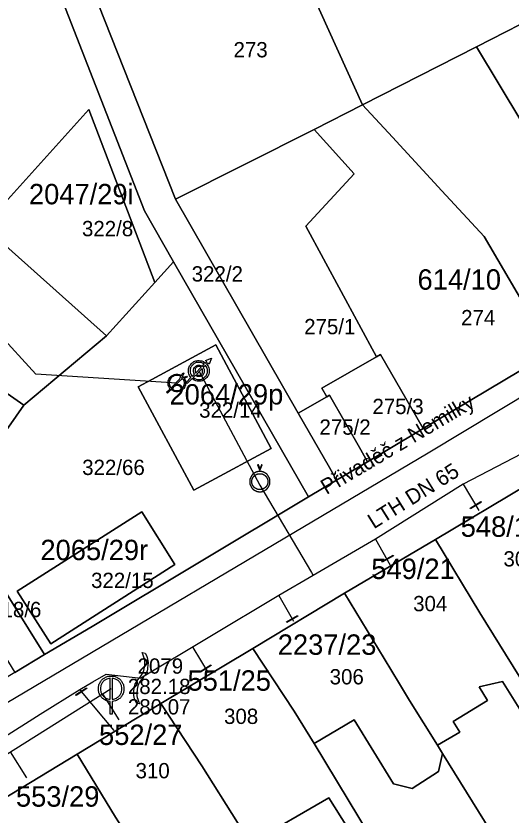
# Model space of a CAD drawing. Extents: x -571312 to -571060, y -1087128 to -1086933.
# Drawn here: x -571251.9 to -571203.4, y -1087085.5 to -1087007.2 of the extents above; entities that cross this region are included whole.
import ezdxf

# ---------------------------------------------------------------- set-up
doc = ezdxf.new("R2010")
doc.units = 0
for name, color, linetype in [('Adresní místo-text', 7, 'Continuous'), ('Armatura vodovodní', 7, 'Continuous'), ('Default', 7, 'Continuous'), ('Kanalizační přípojka', 7, 'Continuous'), ('Kanalizační stoka', 7, 'Continuous'), ('Kanalizační šachta', 7, 'Continuous'), ('Odběrné místo', 7, 'Continuous'), ('Odběrné místo na kanalizaci', 7, 'Continuous'), ('Parcela-polygon', 7, 'Continuous'), ('Parcela-text', 7, 'Continuous'), ('Popis šachty', 7, 'Continuous'), ('Vodovodní přípojka', 7, 'Continuous'), ('Vodovodní řad', 7, 'Continuous'), ('Vodovodní šachta', 7, 'Continuous'), ('Změna stáří vedení', 7, 'Continuous'), ('Řad vodovodní označení', 7, 'Continuous'), ('Řad vodovodní popis', 7, 'Continuous')]:
    doc.layers.add(name, color=color, linetype=linetype)

msp = doc.modelspace()

# ---------------------------------------------------------------- linework, layer by layer
at = {"layer": 'Armatura vodovodní'}
for points in [[(-571206.333, -1087054.873), (-571207.404, -1087055.518), (-571207.445, -1087055.451), (-571206.374, -1087054.806), (-571206.333, -1087054.873)], [(-571214.955, -1087060.142), (-571216.043, -1087060.757), (-571216.082, -1087060.689), (-571214.993, -1087060.074), (-571214.955, -1087060.142)], [(-571224.303, -1087066.06), (-571225.392, -1087066.674), (-571225.43, -1087066.606), (-571224.341, -1087065.992), (-571224.303, -1087066.06)], [(-571232.797, -1087070.894), (-571233.864, -1087071.545), (-571233.905, -1087071.479), (-571232.838, -1087070.828), (-571232.797, -1087070.894)], [(-571245.002, -1087073.147), (-571246.056, -1087073.819), (-571246.098, -1087073.753), (-571245.044, -1087073.081), (-571245.002, -1087073.147)]]:
    msp.add_lwpolyline(points, dxfattribs=at)
at = {"layer": 'Default'}
for points, degree in [([(-571234.791, -1087042.657), (-571235.032, -1087042.38), (-571235.032, -1087042.004), (-571235.032, -1087041.586), (-571234.737, -1087041.291), (-571234.441, -1087040.997), (-571234.022, -1087040.997), (-571233.648, -1087040.997), (-571233.372, -1087041.233)], 3), ([(-571233.49, -1087041.353), (-571233.717, -1087041.164), (-571234.022, -1087041.164), (-571234.372, -1087041.164), (-571234.618, -1087041.41), (-571234.864, -1087041.656), (-571234.864, -1087042.004), (-571234.864, -1087042.31), (-571234.672, -1087042.537)], 3), ([(-571233.264, -1087041.34), (-571233.014, -1087041.62), (-571233.014, -1087042.004), (-571233.014, -1087042.421), (-571233.31, -1087042.716), (-571233.605, -1087043.011), (-571234.022, -1087043.011), (-571234.406, -1087043.011), (-571234.685, -1087042.764)], 3), ([(-571234.566, -1087042.645), (-571234.336, -1087042.842), (-571234.022, -1087042.842), (-571233.675, -1087042.842), (-571233.428, -1087042.597), (-571233.181, -1087042.352), (-571233.181, -1087042.004), (-571233.181, -1087041.69), (-571233.383, -1087041.459)], 3), ([(-571234.452, -1087042.316), (-571234.461, -1087042.3), (-571234.468, -1087042.284), (-571234.53, -1087042.157), (-571234.53, -1087042.016), (-571234.53, -1087041.749), (-571234.386, -1087041.597), (-571234.242, -1087041.446), (-571234.015, -1087041.446), (-571233.867, -1087041.446), (-571233.748, -1087041.517), (-571233.718, -1087041.535), (-571233.693, -1087041.556)], 3), ([(-571233.787, -1087041.65), (-571233.804, -1087041.635), (-571233.823, -1087041.623), (-571233.909, -1087041.569), (-571234.015, -1087041.569), (-571234.165, -1087041.569), (-571234.275, -1087041.672), (-571234.384, -1087041.775), (-571234.384, -1087042.018), (-571234.384, -1087042.129), (-571234.35, -1087042.214)], 3), ([(-571233.592, -1087041.668), (-571233.577, -1087041.691), (-571233.565, -1087041.716), (-571233.502, -1087041.843), (-571233.502, -1087042.004), (-571233.502, -1087042.167), (-571233.568, -1087042.296), (-571233.634, -1087042.425), (-571233.755, -1087042.491), (-571233.876, -1087042.558), (-571234.016, -1087042.558), (-571234.168, -1087042.558), (-571234.287, -1087042.485), (-571234.324, -1087042.461), (-571234.356, -1087042.435)], 3), ([(-571234.263, -1087042.341), (-571234.163, -1087042.436), (-571234.018, -1087042.436), (-571233.856, -1087042.436), (-571233.753, -1087042.323), (-571233.649, -1087042.21), (-571233.649, -1087042.002), (-571233.649, -1087041.872), (-571233.693, -1087041.774), (-571233.694, -1087041.773), (-571233.694, -1087041.772)], 3), ([(-571236.824, -1087043.75), (-571236.876, -1087043.689), (-571236.916, -1087043.615), (-571237.029, -1087043.412), (-571237.029, -1087043.19), (-571237.029, -1087042.967), (-571236.914, -1087042.761), (-571236.799, -1087042.556), (-571236.595, -1087042.445), (-571236.391, -1087042.335), (-571236.174, -1087042.335), (-571235.96, -1087042.335), (-571235.755, -1087042.445), (-571235.736, -1087042.456), (-571235.717, -1087042.468)], 3), ([(-571235.768, -1087042.568), (-571235.789, -1087042.555), (-571235.81, -1087042.543), (-571235.988, -1087042.447), (-571236.174, -1087042.447), (-571236.362, -1087042.447), (-571236.54, -1087042.543), (-571236.717, -1087042.639), (-571236.817, -1087042.818), (-571236.917, -1087042.996), (-571236.917, -1087043.19), (-571236.917, -1087043.383), (-571236.818, -1087043.559), (-571236.786, -1087043.618), (-571236.743, -1087043.669)], 3), ([(-571235.623, -1087042.535), (-571235.567, -1087042.581), (-571235.52, -1087042.638)], 2), ([(-571235.454, -1087042.731), (-571235.445, -1087042.745), (-571235.435, -1087042.761), (-571235.32, -1087042.967), (-571235.32, -1087043.19), (-571235.32, -1087043.412), (-571235.433, -1087043.615), (-571235.546, -1087043.818), (-571235.749, -1087043.931), (-571235.953, -1087044.044), (-571236.174, -1087044.044), (-571236.396, -1087044.044), (-571236.599, -1087043.931), (-571236.673, -1087043.891), (-571236.736, -1087043.838)], 3), ([(-571236.655, -1087043.757), (-571236.604, -1087043.8), (-571236.544, -1087043.833), (-571236.367, -1087043.932), (-571236.174, -1087043.932), (-571235.982, -1087043.932), (-571235.805, -1087043.834), (-571235.629, -1087043.735), (-571235.53, -1087043.559), (-571235.432, -1087043.383), (-571235.432, -1087043.19), (-571235.432, -1087042.996), (-571235.532, -1087042.818), (-571235.543, -1087042.799), (-571235.553, -1087042.782)], 3), ([(-571235.624, -1087042.689), (-571235.648, -1087042.662), (-571235.673, -1087042.639)], 2), ([(-571228.529, -1087051.997), (-571228.686, -1087052.082), (-571228.809, -1087052.204), (-571228.898, -1087052.363)], 2), ([(-571228.043, -1087051.871), (-571228.21, -1087051.871), (-571228.372, -1087051.913), (-571228.529, -1087051.997)], 2), ([(-571228.033, -1087051.594), (-571228.035, -1087051.576), (-571228.039, -1087051.565), (-571228.043, -1087051.56)], 2), ([(-571227.556, -1087051.997), (-571227.715, -1087051.913), (-571227.877, -1087051.871), (-571228.043, -1087051.871)], 2), ([(-571228.019, -1087051.56), (-571228.024, -1087051.569), (-571228.029, -1087051.58), (-571228.033, -1087051.594)], 2), ([(-571227.186, -1087052.363), (-571227.274, -1087052.204), (-571227.398, -1087052.082), (-571227.556, -1087051.997)], 2), ([(-571228.898, -1087052.363), (-571228.987, -1087052.523), (-571229.031, -1087052.689), (-571229.031, -1087052.862)], 2), ([(-571228.823, -1087052.862), (-571228.823, -1087052.726), (-571228.787, -1087052.594), (-571228.717, -1087052.469)], 2), ([(-571228.717, -1087052.469), (-571228.646, -1087052.344), (-571228.549, -1087052.248), (-571228.425, -1087052.18)], 2), ([(-571228.425, -1087052.18), (-571228.3, -1087052.113), (-571228.173, -1087052.08), (-571228.043, -1087052.08)], 2), ([(-571228.043, -1087052.08), (-571227.911, -1087052.08), (-571227.783, -1087052.113), (-571227.659, -1087052.18)], 2), ([(-571227.659, -1087052.18), (-571227.535, -1087052.248), (-571227.437, -1087052.344), (-571227.367, -1087052.469)], 2), ([(-571227.367, -1087052.469), (-571227.296, -1087052.594), (-571227.261, -1087052.726), (-571227.261, -1087052.862)], 2), ([(-571227.052, -1087052.862), (-571227.052, -1087052.689), (-571227.097, -1087052.523), (-571227.186, -1087052.363)], 2), ([(-571229.031, -1087052.862), (-571229.031, -1087053.033), (-571228.987, -1087053.197), (-571228.9, -1087053.353)], 2), ([(-571228.9, -1087053.353), (-571228.812, -1087053.509), (-571228.689, -1087053.631), (-571228.532, -1087053.718)], 2), ([(-571228.718, -1087053.248), (-571228.788, -1087053.125), (-571228.823, -1087052.997), (-571228.823, -1087052.862)], 2), ([(-571228.43, -1087053.536), (-571228.553, -1087053.467), (-571228.649, -1087053.372), (-571228.718, -1087053.248)], 2), ([(-571228.043, -1087053.638), (-571228.178, -1087053.638), (-571228.307, -1087053.604), (-571228.43, -1087053.536)], 2), ([(-571227.654, -1087053.536), (-571227.777, -1087053.604), (-571227.907, -1087053.638), (-571228.043, -1087053.638)], 2), ([(-571227.365, -1087053.248), (-571227.434, -1087053.372), (-571227.531, -1087053.467), (-571227.654, -1087053.536)], 2), ([(-571227.548, -1087053.718), (-571227.391, -1087053.631), (-571227.269, -1087053.509), (-571227.182, -1087053.353)], 2), ([(-571227.261, -1087052.862), (-571227.261, -1087052.997), (-571227.295, -1087053.125), (-571227.365, -1087053.248)], 2), ([(-571227.182, -1087053.353), (-571227.095, -1087053.197), (-571227.052, -1087053.033), (-571227.052, -1087052.862)], 2), ([(-571228.532, -1087053.718), (-571228.375, -1087053.806), (-571228.212, -1087053.85), (-571228.043, -1087053.85)], 2), ([(-571228.043, -1087053.85), (-571227.87, -1087053.85), (-571227.705, -1087053.806), (-571227.548, -1087053.718)], 2), ([(-571240.134, -1087074.597), (-571240.453, -1087073.93), (-571240.383, -1087073.309), (-571240.314, -1087072.688), (-571239.856, -1087072.11), (-571239.398, -1087071.533), (-571239.329, -1087070.914), (-571239.26, -1087070.293), (-571239.578, -1087069.628)], 3), ([(-571239.268, -1087069.663), (-571238.949, -1087070.325), (-571239.018, -1087070.946), (-571239.088, -1087071.567), (-571239.546, -1087072.147), (-571240.003, -1087072.723), (-571240.073, -1087073.344), (-571240.142, -1087073.965), (-571239.824, -1087074.632)], 3), ([(-571242.713, -1087074.418), (-571242.971, -1087074.4), (-571243.233, -1087074.254), (-571243.53, -1087074.09), (-571243.695, -1087073.793), (-571243.86, -1087073.495), (-571243.86, -1087073.17), (-571243.86, -1087072.843), (-571243.692, -1087072.543), (-571243.523, -1087072.242), (-571243.225, -1087072.081), (-571242.927, -1087071.92), (-571242.61, -1087071.92), (-571242.295, -1087071.92), (-571241.996, -1087072.081), (-571241.697, -1087072.242), (-571241.528, -1087072.543), (-571241.36, -1087072.843), (-571241.36, -1087073.17), (-571241.36, -1087073.495), (-571241.525, -1087073.793), (-571241.69, -1087074.09), (-571241.987, -1087074.254), (-571242.249, -1087074.4), (-571242.507, -1087074.418)], 3), ([(-571242.713, -1087072.132), (-571242.91, -1087072.149), (-571243.125, -1087072.264), (-571243.374, -1087072.399), (-571243.513, -1087072.649), (-571243.652, -1087072.899), (-571243.652, -1087073.17), (-571243.652, -1087073.441), (-571243.516, -1087073.688), (-571243.379, -1087073.934), (-571243.13, -1087074.071), (-571242.918, -1087074.191), (-571242.713, -1087074.205)], 3), ([(-571242.507, -1087074.205), (-571242.302, -1087074.191), (-571242.088, -1087074.071), (-571241.841, -1087073.934), (-571241.704, -1087073.688), (-571241.568, -1087073.441), (-571241.568, -1087073.17), (-571241.568, -1087072.899), (-571241.708, -1087072.649), (-571241.848, -1087072.399), (-571242.097, -1087072.264), (-571242.31, -1087072.149), (-571242.507, -1087072.132)], 3)]:
    msp.add_open_spline(points, degree=degree, dxfattribs=at)
at = {"layer": 'Kanalizační přípojka'}
msp.add_line((-571250, -1087042.322), (-571278.716, -1087010.977), dxfattribs=at)
for points in [[(-571236.175, -1087043.19), (-571250, -1087042.322)], [(-571241.819, -1087076.215), (-571243.413, -1087073.674)], [(-571250.882, -1087081.901), (-571252.476, -1087079.36)]]:
    msp.add_lwpolyline(points, dxfattribs=at)
at = {"layer": 'Kanalizační stoka'}
msp.add_lwpolyline([(-571242.61, -1087073.17), (-571257.547, -1087082.542)], dxfattribs=at)
at = {"layer": 'Kanalizační šachta'}
for points in [[(-571242.713, -1087074.205), (-571242.713, -1087072.132)], [(-571242.507, -1087072.132), (-571242.507, -1087074.205)], [(-571242.507, -1087074.418), (-571242.507, -1087075.67), (-571242.713, -1087075.67), (-571242.713, -1087074.418)]]:
    msp.add_lwpolyline(points, dxfattribs=at)
at = {"layer": 'Odběrné místo'}
for points in [[(-571233.244, -1087041.105), (-571233.362, -1087040.994), (-571232.775, -1087040.754), (-571232.997, -1087041.34), (-571233.134, -1087041.21), (-571233.264, -1087041.34)], [(-571234.35, -1087042.214), (-571233.787, -1087041.65)], [(-571233.694, -1087041.772), (-571234.263, -1087042.341)], [(-571233.693, -1087041.556), (-571233.49, -1087041.353)], [(-571233.383, -1087041.459), (-571233.592, -1087041.668)], [(-571233.372, -1087041.233), (-571233.244, -1087041.105)], [(-571234.672, -1087042.537), (-571234.452, -1087042.316)], [(-571234.356, -1087042.435), (-571234.566, -1087042.645)], [(-571234.685, -1087042.764), (-571235.174, -1087043.254), (-571235.275, -1087043.141), (-571234.791, -1087042.657)]]:
    msp.add_lwpolyline(points, dxfattribs=at)
at = {"layer": 'Odběrné místo na kanalizaci'}
for points in [[(-571236.743, -1087043.669), (-571235.9, -1087042.825), (-571235.768, -1087042.568)], [(-571235.717, -1087042.468), (-571235.708, -1087042.449), (-571235.662, -1087042.331), (-571235.601, -1087042.19), (-571235.501, -1087042.235), (-571235.566, -1087042.397), (-571235.614, -1087042.517), (-571235.623, -1087042.535)], [(-571235.52, -1087042.638), (-571235.503, -1087042.629), (-571235.381, -1087042.581), (-571235.231, -1087042.52), (-571235.175, -1087042.614), (-571235.317, -1087042.676), (-571235.435, -1087042.721), (-571235.454, -1087042.731)], [(-571235.553, -1087042.782), (-571235.814, -1087042.916), (-571236.655, -1087043.757)], [(-571235.673, -1087042.639), (-571235.722, -1087042.737), (-571235.624, -1087042.689)], [(-571236.736, -1087043.838), (-571236.748, -1087043.85), (-571236.838, -1087043.94), (-571237.089, -1087044.191), (-571237.177, -1087044.102), (-571236.925, -1087043.851), (-571236.836, -1087043.762), (-571236.824, -1087043.75)]]:
    msp.add_lwpolyline(points, dxfattribs=at)
at = {"layer": 'Parcela-polygon'}
for points in [[(-571208.98, -1086985.45), (-571218.36, -1086988.9), (-571217.04, -1086992.42), (-571226.94, -1086996.1), (-571217.97, -1087015.93), (-571206.82, -1087010.23), (-571199.65, -1087006.57), (-571207.52, -1086988.77)], [(-571223.27, -1087054.35), (-571220.52, -1087052.71), (-571221.22, -1087051.48), (-571224.28, -1087046.14), (-571236.3, -1087025.16), (-571245.11, -1087002.85), (-571249.74, -1086991.11), (-571253.67, -1086989.56), (-571252.89, -1086991.54), (-571239.35, -1087026.31), (-571236.49, -1087031.3)], [(-571280.58, -1087024.78), (-571275.83, -1087028.1), (-571251.17, -1087045.35), (-571243.07, -1087038.57), (-571255.12, -1087027.8), (-571244.8, -1087016.38), (-571238.33, -1087033.34), (-571236.49, -1087031.3), (-571239.35, -1087026.31), (-571252.89, -1086991.54), (-571254.35, -1086990.89), (-571254.9, -1086994.13), (-571258.67, -1087000.06), (-571285.9, -1087020.87), (-571280.44, -1087024.63)], [(-571226.94, -1086996.1), (-571236.54, -1086999.66), (-571245.11, -1087002.85), (-571236.3, -1087025.16), (-571222.72, -1087018.32), (-571217.97, -1087015.93)], [(-571184.85, -1087031.35), (-571199.65, -1087006.57), (-571206.82, -1087010.23), (-571202.38, -1087017.63), (-571197.08, -1087017.54), (-571187.38, -1087032.88)], [(-571197.08, -1087017.54), (-571202.38, -1087017.63), (-571206.82, -1087010.23), (-571217.97, -1087015.93), (-571215.05, -1087019.09), (-571210.21, -1087024.35), (-571206.07, -1087028.84), (-571200.94, -1087037.57), (-571199.42, -1087040.15), (-571187.38, -1087032.88)], [(-571210.21, -1087024.35), (-571215.05, -1087019.09), (-571217.97, -1087015.93), (-571222.72, -1087018.32), (-571218.79, -1087022.67), (-571223.54, -1087027.82), (-571216.62, -1087040.62), (-571216.21, -1087040.39), (-571212.67, -1087046.57), (-571212.04, -1087047.66), (-571199.42, -1087040.15), (-571200.94, -1087037.57), (-571206.07, -1087028.84)], [(-571243.07, -1087038.57), (-571238.33, -1087033.34), (-571244.8, -1087016.38), (-571255.12, -1087027.8)], [(-571236.3, -1087025.16), (-571224.28, -1087046.14), (-571221.49, -1087044.54), (-571221.98, -1087043.7), (-571216.62, -1087040.62), (-571223.54, -1087027.82), (-571218.79, -1087022.67), (-571222.72, -1087018.32)], [(-571244.48, -1087067.05), (-571223.27, -1087054.35), (-571236.49, -1087031.3), (-571238.33, -1087033.34), (-571243.07, -1087038.57), (-571251.17, -1087045.35), (-571257.9, -1087054.96), (-571254.11, -1087057.62), (-571253.82, -1087062.35), (-571250.71, -1087067.3), (-571249.13, -1087069.82)], [(-571226.93, -1087049.61), (-571232.36, -1087039.46), (-571238.63, -1087042.83), (-571239.96, -1087043.55), (-571234.52, -1087053.69), (-571233.23, -1087053)], [(-571238.63, -1087042.83), (-571232.36, -1087039.46), (-571226.93, -1087049.61), (-571233.23, -1087053), (-571234.52, -1087053.69), (-571239.96, -1087043.55)], [(-571216.62, -1087040.62), (-571221.98, -1087043.7), (-571221.49, -1087044.54), (-571221.23, -1087044.39), (-571218.14, -1087049.74), (-571217.5, -1087050.91), (-571212.62, -1087048.01), (-571212.04, -1087047.66), (-571212.67, -1087046.57), (-571216.21, -1087040.39)], [(-571217.5, -1087050.91), (-571218.14, -1087049.74), (-571221.23, -1087044.39), (-571221.49, -1087044.54), (-571224.28, -1087046.14), (-571221.22, -1087051.48), (-571220.52, -1087052.71)], [(-571210.82, -1087058.52), (-571206.5, -1087065.72), (-571199.38, -1087077.18), (-571193.1, -1087073.51), (-571190.45, -1087071.91), (-571191.52, -1087070.21), (-571191.96, -1087069.51), (-571193.15, -1087067.62), (-571195.24, -1087064.3), (-571197.12, -1087061.3), (-571197.8, -1087060.21), (-571201.86, -1087053.18)], [(-571251.81, -1087063.6), (-571248.52, -1087068.76), (-571236.37, -1087060.99), (-571239.62, -1087055.81)], [(-571251.81, -1087063.6), (-571239.62, -1087055.81), (-571236.37, -1087060.99), (-571248.52, -1087068.76)], [(-571219.73, -1087063.8), (-571215.85, -1087070.21), (-571214.37, -1087072.67), (-571213.37, -1087074.33), (-571210.64, -1087078.7), (-571208.46, -1087077.42), (-571209.1, -1087076.39), (-571205.73, -1087074.32), (-571206.54, -1087072.99), (-571204.26, -1087072.46), (-571200.02, -1087079.25), (-571196.13, -1087085.46), (-571194.74, -1087084.64), (-571199.38, -1087077.18), (-571206.5, -1087065.72), (-571210.82, -1087058.52)], [(-571252.04, -1087071.56), (-571249.13, -1087069.82), (-571250.71, -1087067.3), (-571253.82, -1087062.35), (-571254.05, -1087061.99), (-571256.95, -1087063.77), (-571256.72, -1087064.14), (-571253.59, -1087069.11)], [(-571210.13, -1087079.52), (-571210.64, -1087078.7), (-571213.37, -1087074.33), (-571214.37, -1087072.67), (-571215.85, -1087070.21), (-571219.73, -1087063.8), (-571228.73, -1087069.23), (-571224.67, -1087075.35), (-571222.73, -1087078.55), (-571218.81, -1087076.21), (-571214.96, -1087082.48), (-571213.1, -1087082.94), (-571210.53, -1087081.27)], [(-571228.73, -1087069.23), (-571237.74, -1087074.6), (-571233.74, -1087080.71), (-571230.24, -1087086.27), (-571228.95, -1087088.31), (-571221.28, -1087083.87), (-571213.81, -1087095.76), (-571212.71, -1087095.11), (-571222.73, -1087078.55), (-571224.67, -1087075.35)], [(-571205.73, -1087074.32), (-571209.1, -1087076.39), (-571208.46, -1087077.42), (-571210.64, -1087078.7), (-571210.13, -1087079.52), (-571203.69, -1087089.94), (-571196.13, -1087085.46), (-571200.02, -1087079.25), (-571204.26, -1087072.46), (-571206.54, -1087072.99)], [(-571230.24, -1087086.27), (-571233.74, -1087080.71), (-571237.74, -1087074.6), (-571245.94, -1087079.58), (-571242.19, -1087085.75), (-571240.73, -1087088.03), (-571238.58, -1087091.38), (-571237.41, -1087093.2), (-571228.95, -1087088.31)], [(-571203.69, -1087089.94), (-571210.13, -1087079.52), (-571210.53, -1087081.27), (-571213.1, -1087082.94), (-571214.96, -1087082.48), (-571218.81, -1087076.21), (-571222.73, -1087078.55), (-571212.71, -1087095.11)], [(-571254.21, -1087084.57), (-571253.39, -1087085.95), (-571251.65, -1087088.8), (-571249.96, -1087091.66), (-571249.14, -1087093.07), (-571242.3, -1087104.3), (-571239.74, -1087102.77), (-571239.52, -1087103.15), (-571239.41, -1087103.08), (-571243.72, -1087094.92), (-571238.58, -1087091.38), (-571240.73, -1087088.03), (-571242.19, -1087085.75), (-571245.94, -1087079.58)], [(-571228.95, -1087088.31), (-571221.44, -1087100.23), (-571213.81, -1087095.76), (-571221.28, -1087083.87)]]:
    msp.add_lwpolyline(points, close=True, dxfattribs=at)
for points in [[(-571152.8, -1087012.2), (-571165.57, -1087019.85), (-571178.15, -1087027.35), (-571184.85, -1087031.35), (-571187.38, -1087032.88), (-571199.42, -1087040.15), (-571212.04, -1087047.66), (-571212.62, -1087048.01), (-571217.5, -1087050.91), (-571220.52, -1087052.71), (-571223.27, -1087054.35), (-571244.48, -1087067.05), (-571249.13, -1087069.82), (-571252.04, -1087071.56), (-571254.73, -1087073.17), (-571257.35, -1087074.74), (-571258.59, -1087075.48), (-571259.95, -1087076.45), (-571260.789, -1087077.05)], [(-571254.973, -1087086.903), (-571253.39, -1087085.95), (-571254.21, -1087084.57), (-571245.94, -1087079.58), (-571237.74, -1087074.6), (-571228.73, -1087069.23), (-571219.73, -1087063.8), (-571210.82, -1087058.52), (-571201.86, -1087053.18), (-571190.56, -1087046.39), (-571189.72, -1087045.85), (-571184.97, -1087043.06), (-571183.51, -1087042.2), (-571177.42, -1087038.4), (-571168.35, -1087033.04), (-571159.39, -1087027.73), (-571150.57, -1087022.45)], [(-571284.641, -1087036.645), (-571282.71, -1087038), (-571274.33, -1087043.89), (-571274.24, -1087043.77), (-571267.11, -1087048.8), (-571264.33, -1087050.75), (-571258.05, -1087055.18), (-571257.9, -1087054.96), (-571251.17, -1087045.35), (-571275.83, -1087028.1), (-571280.58, -1087024.78), (-571286.558, -1087033.398)]]:
    msp.add_lwpolyline(points, dxfattribs=at)
at = {"layer": 'Vodovodní přípojka'}
for p, q in [((-571208.123, -1087053.111), (-571206.576, -1087055.682)), ((-571216.72, -1087058.494), (-571215.283, -1087061.04)), ((-571226.167, -1087064.027), (-571224.746, -1087066.548)), ((-571234.604, -1087069.132), (-571233.09, -1087071.614))]:
    msp.add_line(p, q, dxfattribs=at)
for points in [[(-571234.025, -1087042.004), (-571228.041, -1087053.194), (-571222.974, -1087061.78), (-571222.809, -1087062.06)], [(-571245.69, -1087073.23), (-571245.55, -1087073.45), (-571242.359, -1087077.272)]]:
    msp.add_lwpolyline(points, dxfattribs=at)
at = {"layer": 'Vodovodní řad'}
for points in [[(-571259.706, -1087078.885), (-571257.725, -1087077.417), (-571211.542, -1087050.048), (-571176.933, -1087029.184), (-571227.483, -1086941.667)], [(-571118.52, -1087001.2), (-571121.219, -1087002.471), (-571130.326, -1087008.201), (-571146.537, -1087017.741), (-571155.651, -1087023.106), (-571186.289, -1087039.932), (-571190.097, -1087043.426), (-571196.691, -1087047.158), (-571208.123, -1087053.111), (-571216.72, -1087058.494), (-571222.809, -1087062.06), (-571226.167, -1087064.027), (-571239.701, -1087072.13)], [(-571258.288, -1087081.288), (-571256.482, -1087080.103), (-571253.438, -1087078.107), (-571249.564, -1087075.668), (-571245.69, -1087073.23), (-571244.399, -1087072.489), (-571243.107, -1087071.749), (-571241.404, -1087071.94), (-571239.701, -1087072.13)]]:
    msp.add_lwpolyline(points, dxfattribs=at)
at = {"layer": 'Vodovodní šachta'}
for points in [[(-571228.043, -1087051.56), (-571228.166, -1087051.201), (-571228.262, -1087051.201), (-571228.067, -1087051.704)], [(-571228.067, -1087051.704), (-571227.999, -1087051.704), (-571227.801, -1087051.201), (-571227.89, -1087051.201), (-571228.019, -1087051.56)]]:
    msp.add_lwpolyline(points, dxfattribs=at)
at = {"layer": 'Změna stáří vedení'}
for points in [[(-571239.578, -1087069.628), (-571239.268, -1087069.663)], [(-571239.824, -1087074.632), (-571240.134, -1087074.597)]]:
    msp.add_lwpolyline(points, dxfattribs=at)

# ---------------------------------------------------------------- texts
at = {"layer": 'Adresní místo-text'}
for s, p in [('2047/29i', (-571250.668, -1087025.67)), ('614/10', (-571212.591, -1087034.04)), ('2064/29p', (-571236.895, -1087045.3)), ('548/19', (-571208.361, -1087058.27)), ('2065/29r', (-571249.543, -1087060.56)), ('549/21', (-571217.121, -1087062.41)), ('2237/23', (-571226.288, -1087069.84)), ('551/25', (-571235.131, -1087073.36)), ('552/27', (-571243.801, -1087078.68)), ('553/29', (-571251.941, -1087084.73))]:
    msp.add_text(s, height=2, dxfattribs=at).set_placement(p)
at = {"layer": 'Parcela-text'}
for s, p in [('273', (-571230.62, -1087011.26)), ('322/8', (-571245.47, -1087028.8)), ('322/2', (-571234.72, -1087033.24)), ('274', (-571208.32, -1087037.53)), ('275/1', (-571223.7, -1087038.41)), ('275/3', (-571217.01, -1087046.24)), ('322/14', (-571233.99, -1087046.59)), ('275/2', (-571222.2, -1087048.26)), ('322/66', (-571245.45, -1087052.21)), ('302', (-571204.17, -1087061.18)), ('322/15', (-571244.58, -1087063.29)), ('304', (-571213.02, -1087065.57)), ('318/6', (-571254.47, -1087066.15)), ('306', (-571221.2, -1087072.74)), ('308', (-571231.55, -1087076.62)), ('310', (-571240.22, -1087081.95))]:
    msp.add_text(s, height=1.5, dxfattribs=at).set_placement(p)
at = {"layer": 'Popis šachty'}
for s, p in [('2079', (-571240.022, -1087071.689)), ('282.18', (-571240.972, -1087073.689)), ('280.07', (-571240.972, -1087075.689))]:
    msp.add_text(s, height=1.5, dxfattribs=at).set_placement(p)
at = {"layer": 'Řad vodovodní označení'}
msp.add_text('Přivaděč z Nemilky', height=1.5, rotation=30.65186, dxfattribs=at).set_placement((-571221.513, -1087054.175))
at = {"layer": 'Řad vodovodní popis'}
msp.add_text('LTH DN 65', height=1.5, rotation=32.05269, dxfattribs=at).set_placement((-571216.869, -1087057.542))

doc.saveas('drawing.dxf')
